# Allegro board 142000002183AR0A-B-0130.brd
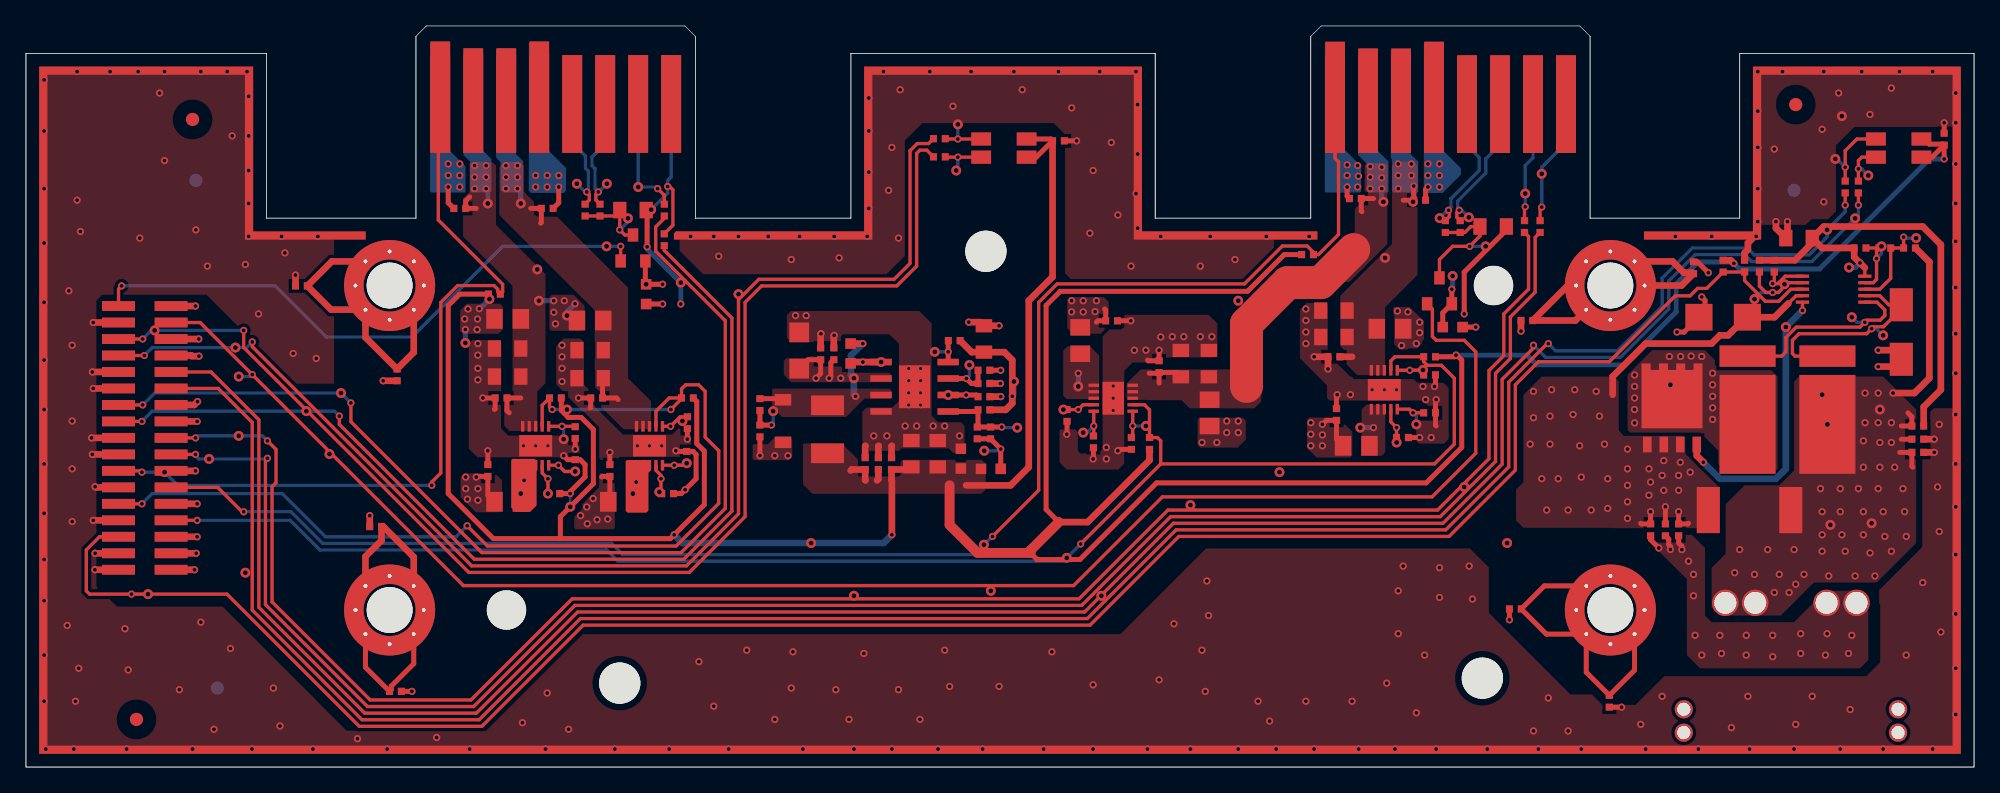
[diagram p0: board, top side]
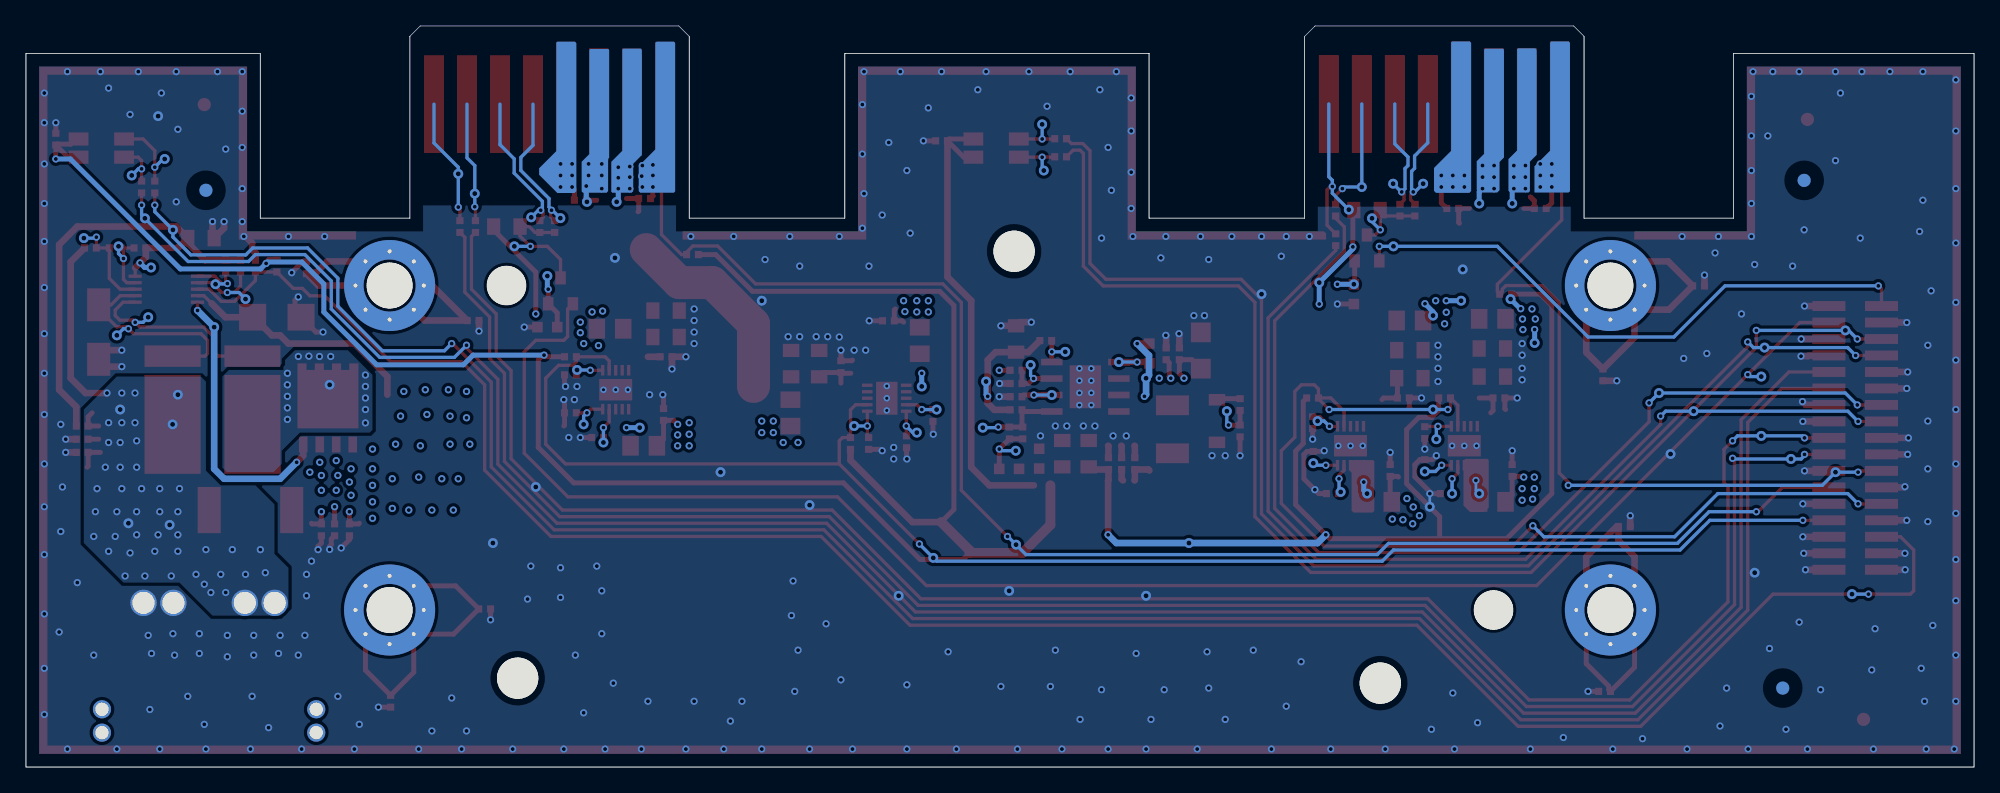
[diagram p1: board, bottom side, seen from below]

Outline 150 x 57.1 mm; copper layers: TOP, G2, V3, BOTTOM. Coordinates in mm from the lower left corner of the outline.
Outline path: 30.03,56.3 30.03,42.29 18.51,42.29 18.51,54.99 0,54.99 0,0 150,0 150,54.99 131.96,54.99 131.96,42.29 120.44,42.29 120.44,56.3 ; 51.54,56.3 51.54,42.29 63.52,42.29 63.52,54.99 86.95,54.99 86.95,42.29 98.93,42.29 98.93,56.3

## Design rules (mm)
constraint set DEFAULT: min track width 0.254
net group CLS_POWER: nets VCC_CL_FAN7F VCC_CL_FAN7R
net group DIFF_FAN7: nets FAN7_IN_PWM FAN7_OUT_PWM
net group DIFF_FAN8: nets FAN8_IN_PWM FAN8_OUT_PWM
net group CLS_GND: nets FAN7_S_GND FAN8_S_GND LGND_FAN12V LGND_VDD3P3
net group CLS_PWM: nets FAN7_PWM_P FAN8_PWM_P PWM_OUT7 PWM_OUT8

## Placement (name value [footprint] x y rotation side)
C1  1000pF/50V  [CC0402]  21.21 37.07 270 top
C2  1000pF/50V  [CC0402]  26.92 18.53 270 top
C3  1000pF/50V  [CC0402]  28.45 5.83 90 top
C4  1000pF/50V  [CC0402]  28.57 30.21 0 top
C5  1000pF  [CC0402]  33.4 43.04 90 top
C6  0.1uF  [CC0402]  35.57 22.85 0 top
C7  0.1uF/16V  [CC0402]  36.58 28.44 270 top
C8  22uF/16V  [CC0805]  37.09 32.25 270 top
C9  10uF/16V  [CC0805]  37.09 30.09 270 top
C10  1000pF  [CC0402]  40.14 43.04 90 top
C11  0.1uF/16V  [CC0402]  40.65 21.07 270 top
C12  0.1uF/16V  [CC0402]  42.29 25.77 180 top
C13  22uF/16V  [CC0805]  43.44 32.12 270 top
C14  10uF/16V  [CC0805]  43.44 29.96 270 top
C15  0.1uF  [CC0402]  43.94 28.44 270 top
C16  0.1uF/16V  [CC0402]  44.96 22.85 0 top
C17  0.1uF/16V  [CC0402]  49.41 21.07 270 top
C18  0.1uF/16V  [CC0402]  50.93 26.53 180 top
C19  2200pF/50V  [CC0402]  56.52 25.9 0 top
C20  22uF/16V  [CC1206]  59.54 32.09 180 top
C21  1nF/50V  [CC0402]  61.19 31.84 180 top
C22  0.1uF/16V  [CC0402]  62.2 31.84 180 top
C23  0.1uF/50V  [CC0603]  63.5 31.87 180 top
C24  1uF/6.3V  [CC0402]  64.62 23.38 180 top
C25  0.1uF/16V  [CC0402]  65.63 23.38 180 top
C26  1uF/6.3V  [CC0402]  66.65 23.38 180 top
C27  22uF/6.3V  [CC0805]  68.17 24.14 180 top
C28  22uF/6.3V  [CC0805]  70.21 24.14 180 top
C29  8200pF/16V  [CC0402]  71.48 32.86 90 top
C30  10uF/6.3V  [CC0603]  71.98 23.76 180 top
C31  22pF/50V  [CC0402]  73.25 25.74 180 top
C32  10pF  [CC0402]  73.76 29.55 90 top
C33  0.47uF/6.3V  [CC0402]  73.76 28.54 90 top
C34  0.1uF/16V  [CC0402]  79.5 48.25 90 top
C35  0.1uF/16V  [CC0402]  80.16 27.09 180 top
C36  0.1uF/16V  [CC0402]  83.59 34.38 270 top
C37  0.1uF/16V  [CC0402]  85.12 24.93 180 top
C38  0.1uF/16V  [CC0402]  87.25 30.85 180 top
C39  10uF/16V  [CC0805]  88.93 31.08 180 top
C40  22uF/16V  [CC0805]  91.08 31.08 180 top
C41  22uF/16V  [CC0805]  100.71 35.17 270 top
C42  10uF/16V  [CC0805]  100.71 33.14 270 top
C43  0.1uF/16V  [CC0402]  100.71 31.61 270 top
C44  0.1uF/16V  [CC0402]  100.91 27.17 0 top
C45  1000pF  [CC0402]  102.36 43.8 90 top
C46  0.1uF/16V  [CC0402]  105.99 25.39 270 top
C47  1000pF  [CC0402]  107.31 43.68 90 top
C48  0.1uF/16V  [CC0402]  108.08 30.21 270 top
C49  1000pF/50V  [CC0402]  114.68 12.18 270 top
C50  1000pF/50V  [CC0402]  115.57 34.41 270 top
C51  1000pF/50V  [CC0402]  121.92 5.07 0 top
C52  1000pF/50V  [CC0402]  125.09 18.28 0 top
C53  1000pF/50V  [CC0402]  126.24 18.28 0 top
C54  0.1uF/16V  [CC0402]  127.25 18.28 0 top
C55  1000pF/50V  [CC0402]  128.4 38.47 180 top
C56  0.1uF/16V  [CC0402]  132.33 38.6 180 top
C57  6800pF  [CC0402]  134.62 38.6 180 top
C58  1nF/50V  [CC0402]  145.67 26.28 90 top
C59  0.1uF/16V  [CC0402]  145.67 25.26 90 top
C60  1nF/50V  [CC0402]  145.67 24.25 90 top
C61  0.1uF/16V  [CC0402]  147.7 48.38 180 top
CONN1  LCB25-G3424S01C-04  [CONNM_1D27X4D05_2X17SP_36D09W]  9.15 25.36 270 top
CONN2  CONN_POWER_4P_G4  [CONN_2D3_4DP_18D2W12D3L_PIP]  135.9 12.65 180 top
D1  SS1040  [SOD123_3D28_2SP_AC]  58.29 26.66 0 top
D2  1SMA4744  [DO214AC_3D73_2SP_2D7W4D3L2D44H]  130.68 34.66 0 top
D3  P4SMAJ58A  [DIOZENER_2SP_2D6WX4D5L_AC]  144.4 33.52 0 top
H1  *SCREW_8_1  [MTH_276C138D_8DP_OSP]  28 37.1 0 top
H2  *SCREW_8_1  [MTH_276C138D_8DP_OSP]  28 12.1 0 top
H3  *SCREW_8_1  [MTH_276C138D_8DP_OSP]  122 37.1 0 top
H4  *SCREW_8_1  [MTH_276C138D_8DP_OSP]  122 12.1 0 top
L1  100MHz/5A  [LC0805]  37.09 34.53 90 top
L2  100MHz/5A  [LC0805]  37.09 20.44 90 top
L3  100MHz/5A  [LC0805]  43.44 34.41 90 top
L4  100MHz/5A  [LC0805]  45.85 20.44 90 top
L5  1.5uH/4.5A  [CHOKE_3D7_2SP_4W4D5L2H]  61.72 26.02 270 top
L6  100MHz/5A  [LC0805]  81.18 32.86 0 top
L7  100MHz/5A  [LC0805]  91.14 27.29 180 top
L8  100MHz/5A  [LC0805]  102.43 24.75 90 top
L9  100MHz/5A  [LC0805]  105.03 33.77 270 top
LED1  LED2_1  [LED_1D4X3D5_4SP_2D7W3D2L1D1H_AC]  75.3 47.69 0 top
LED2  LED2_1  [LED_1D4X3D5_4SP_2D7W3D2L1D1H_AC]  144.2 47.69 0 top
NOREF  -  []  75.3 47.69 0 top
NOREF#2  -  []  18.51 54.99 0 top
NOREF#3  -  [unnamed#2]  112.14 6.85 0 top
NOREF#4  -  []  119.64 57.1 0 top
NOREF#5  -  []  122 37.1 0 top
NOREF#6  -  []  -35.56 -22.11 0 top
NOREF#7  -  []  37 12.1 0 top
NOREF#8  -  [unnamed#2]  136.27 51.04 0 top
NOREF#9  -  []  28 37.1 0 top
NOREF#10  -  []  51.54 56.3 0 top
NOREF#11  -  [unnamed#2]  113 37.1 0 top
NOREF#12  -  []  75.3 47.69 0 top
NOREF#13  -  [unnamed#2]  12.83 49.9 0 top
NOREF#14  -  []  28 37.1 0 top
NOREF#15  -  []  113 37.1 0 top
NOREF#16  -  []  0 0 0 top
NOREF#17  -  []  120.44 56.3 0 top
NOREF#18  -  []  92.84 5.96 0 top
NOREF#19  -  []  130.85 12.65 0 top
NOREF#20  -  []  150 0 0 top
NOREF#21  -  []  0 0 0 top
NOREF#22  -  [unnamed#2]  45.72 6.47 0 top
NOREF#23  -  []  0 54.99 0 top
NOREF#24  -  []  131.96 54.99 0 top
NOREF#25  -  []  144.2 47.69 0 top
NOREF#26  -  []  18.51 42.29 0 top
NOREF#27  -  [unnamed#2]  73.91 39.74 0 top
NOREF#28  -  []  86.95 54.99 0 top
NOREF#29  -  [unnamed#2]  37 12.1 0 top
NOREF#30  -  []  98.93 56.3 0 top
NOREF#31  -  []  9.15 25.36 0 top
NOREF#32  -  [unnamed#2]  8.51 3.67 0 top
NOREF#33  -  []  37 12.1 0 top
NOREF#34  -  []  130.85 12.65 0 top
NOREF#35  -  []  28 12.1 0 top
NOREF#36  -  []  113 37.1 0 top
NOREF#37  -  []  63.52 54.99 0 top
NOREF#38  -  []  30.03 56.3 0 top
NOREF#39  -  []  325.75 -30.7 0 top
NOREF#40  -  []  511.81 -36.71 0 top
NOREF#41  -  []  0 0 0 top
NOREF#42  -  [unnamed#2]  13.08 45.2 180 bottom
NOREF#43  -  [unnamed#2]  136.14 44.44 180 bottom
NOREF#44  -  [unnamed#2]  14.73 6.08 180 bottom
Q1  N-CH  [SOT23_1D9X2D_3SP_1D3W3L_GSD]  46.74 39.99 0 top
Q2  N-CH  [SOT23_1D9X2D_3SP_1D3W3L_GSD]  108.84 36.69 0 top
Q3  N-CH/30V/200A  [SO8_3D75X1D27_5SP]  126.75 27.67 270 top
R1  10Kohm  [RC0402]  36.07 36.44 90 top
R2  4.7Kohm  [RC0402]  40.77 28.44 270 top
R3  2.8Kohm  [RC0402]  42.29 23.23 0 top
R4  0ohm  [RC0402]  43.06 42.91 0 top
R5  0ohm  [RC0402]  44.2 42.91 0 top
R6  7.5Kohm  [RC0805]  46.74 42.91 90 top
R7  0ohm  [RC0603]  47.75 36.44 180 top
R8  0ohm  [RC0402]  49.15 40.63 0 top
R9  0ohm  [RC0402]  49.15 42.91 180 top
R10  2.8Kohm  [RC0402]  50.88 23.86 0 top
R11  4.7Kohm  [RC0402]  50.93 28.44 270 top
R12  2.2ohm  [RC0402]  56.52 27.93 180 top
R13  110ohm  [RC0402]  70.33 48.41 90 top
R14  110ohm  [RC0402]  70.33 47.02 90 top
R15  0ohm  [RC0805]  73.76 32.98 0 top
R16  10Kohm  [RC0402]  73.76 30.57 90 top
R17  10Kohm  [RC0402]  73.76 27.52 90 top
R18  33.2Kohm  [RC0402]  74.27 25.74 0 top
R19  49.9ohm  [RC0603]  74.3 22.98 270 top
R20  2.8Kohm  [RC0402]  82.19 25.06 180 top
R21  4.7Kohm  [RC0402]  86.51 24.93 180 top
R22  10Kohm  [RC0402]  98.68 39.49 90 top
R23  4.7Kohm  [RC0402]  108.08 31.61 270 top
R24  2.8Kohm  [RC0402]  108.08 27.29 270 top
R25  0ohm  [RC0402]  109.29 41.64 0 top
R26  0ohm  [RC0603]  109.86 33.9 270 top
R27  0ohm  [RC0402]  110.43 41.64 0 top
R28  7.5Kohm  [RC0805]  112.97 41.64 90 top
R29  0ohm  [RC0402]  115.39 41.64 180 top
R30  0ohm  [RC0402]  116.59 41.64 0 top
R31  4.7Kohm  [RC0402]  130.68 38.6 180 top
R32  0.001ohm  [RC2512]  132.72 19.8 90 top
R33  8.87Kohm  [RC0402]  133.48 38.6 0 top
R34  0.001ohm  [RC_6D15_2SP_9D14W9D4L]  135.64 27.55 0 top
R35  0ohm  [RC0805]  136.53 40.76 270 top
R36  110ohm  [RC0402]  140.08 44.69 180 top
R37  110ohm  [RC0402]  141.1 44.69 180 top
R38  4.64Kohm  [RC0402]  141.22 39.99 90 top
R39  3.24Kohm  [RC0402]  143.13 39.99 90 top
R40  23.7Kohm  [RC0402]  145.03 39.99 90 top
U1  SY6875ADBC  [DFN_D5X3D_10SP_3WL1H_G1]  39.25 24.75 0 top
U2  Golden Finger  [GOLD_FINGER_2D54_8X2SP]  49.68 51.09 0 top
U3  SY6875ADBC  [DFN_D5X3D_10SP_3WL1H_G1]  48.01 24.75 0 top
U4  TPS54329DDAR  [SOP_1D27X5D165_8SP_3D9W_G95X130]  68.43 29.3 0 top
U5  SY6875ADBC  [DFN_D5X3D_10SP_3WL1H_G1]  83.72 28.42 270 top
U6  SY6875ADBC  [DFN_D5X3D_10SP_3WL1H_G1]  104.59 29.07 0 top
U7  Golden Finger  [GOLD_FINGER_2D54_8X2SP]  118.58 51.07 0 top
U8  LM5069MM-2/NOPB  [MSOP_D5X4D8_10SP_3WL1D09H]  139.19 36.82 90 top

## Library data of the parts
C1-C61 = C_NP
CONN1 = PIN HEADER_MALE_17PX2R
CONN2 = CONN_POWER_4P_G4
D1 = DIODE1_1
D2 = ZENER1_1
D3 = TVS1_1
H1-H4 = SCREW_8_1
L1-L4 L6-L9 = BEAD
L5 = POWER CHOKE
LED1 LED2 = LED2_1
Q1 Q2 = NMOS1_1
Q3 = NMOS1_6
R1-R15 R17-R33 R35-R40 = R: tolerance: 1%
R16 = R: room: 71
R34 = R_4P: tolerance: 1%
U1 U3 U5 U6 = MONITOR_CUR_SILERGY_SY6875
U2 U7 = Golden Finger
U4 = DC_DC_TI_TPS54329
U8 = HOT SWAP_NS_LM5069

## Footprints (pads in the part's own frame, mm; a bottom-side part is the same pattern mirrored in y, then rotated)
CC0402
  rect 0.559x0.539 smd: 1(0,0.454) 2(0,-0.454)
CC0603
  rect 0.813x0.813 smd: 1(0,0.762) 2(0,-0.762)
CC0805
  rect 1.27x1.016 smd: 1(0,1.016) 2(0,-1.016)
CC1206
  rect 1.524x1.524 smd: 1(0,1.397) 2(0,-1.397)
CHOKE_3D7_2SP_4W4D5L2H
  rect 1.524x2.54 smd: 1(-1.85,0) 2(1.85,0)
CONN_2D3_4DP_18D2W12D3L_PIP
  round 1.397 hole 1.016: G1(-8.25,10) G2(-8.25,8.2) G3(8.25,10) G4(8.25,8.2)
  round 2.032 hole 1.702: P1(5.05,0) P2(2.75,0) P3(-2.75,0) P4(-5.05,0)
CONNM_1D27X4D05_2X17SP_36D09W
  rect 0.762x2.54 smd: 1(-10.16,-2.025) 2(-10.16,2.025) 3(-8.89,-2.025) 4(-8.89,2.025) 5(-7.62,-2.025) 6(-7.62,2.025) 7(-6.35,-2.025) 8(-6.35,2.025) 9(-5.08,-2.025) 10(-5.08,2.025) 11(-3.81,-2.025) 12(-3.81,2.025) 13(-2.54,-2.025) 14(-2.54,2.025) 15(-1.27,-2.025) 16(-1.27,2.025) 17(0,-2.025) 18(0,2.025) 19(1.27,-2.025) 20(1.27,2.025) 21(2.54,-2.025) 22(2.54,2.025) 23(3.81,-2.025) 24(3.81,2.025) 25(5.08,-2.025) 26(5.08,2.025) 27(6.35,-2.025) 28(6.35,2.025) 29(7.62,-2.025) 30(7.62,2.025) 31(8.89,-2.025) 32(8.89,2.025) 33(10.16,-2.025) 34(10.16,2.025)
DFN_D5X3D_10SP_3WL1H_G1
  rect 0.254x0.813 smd: 1(-1,-1.5) 2(-0.5,-1.5) 3(0,-1.5) 4(0.5,-1.5) 5(1,-1.5) 6(1,1.5) 7(0.5,1.5) 8(0,1.5) 9(-0.5,1.5) 10(-1,1.5)
  rect 2.54x1.651 smd: G1(0,0)
DIOZENER_2SP_2D6WX4D5L_AC
  rect 1.778x2.54 smd: A(0,-2.1) C(0,2.1)
DO214AC_3D73_2SP_2D7W4D3L2D44H
  rect 2.083x2.057 smd: A(-1.865,0) C(1.865,0)
GOLD_FINGER_2D54_8X2SP
  rect 1.524x7.518 smd: 1(0,0) 2(-2.54,0) 3(-5.08,0) 4(-7.62,0) 9(0,0) 10(-2.54,0) 11(-5.08,0) 12(-7.62,0) 13(-10.16,0) 14(-12.7,0) 15(-15.24,0) 16(-17.78,0)
  rect 1.524x8.56 smd: 5(-10.16,0.533) 8(-17.78,0.533)
  rect 1.524x8.052 smd: 6(-12.7,0.267) 7(-15.24,0.267)
LC0805
  rect 1.524x1.27 smd: 1(0,1.016) 2(0,-1.016)
LED_1D4X3D5_4SP_2D7W3D2L1D1H_AC
  rect 1.524x1.016 smd: A1(1.75,-0.7) A2(1.75,0.7) C1(-1.75,-0.7) C2(-1.75,0.7)
MSOP_D5X4D8_10SP_3WL1D09H
  rect 0.254x1.016 smd: 1(-1,-2.4) 2(-0.5,-2.4) 3(0,-2.4) 4(0.5,-2.4) 5(1,-2.4) 6(1,2.4) 7(0.5,2.4) 8(0,2.4) 9(-0.5,2.4) 10(-1,2.4)
MTH_276C138D_8DP_OSP
  round 3.505 hole 3.505 unplated: (0,0)
  round 0.889 hole 0.305: 1(0,2.629) 2(1.859,1.859) 3(2.629,0) 4(1.859,-1.859) 5(0,-2.629) 6(-1.859,-1.859) 7(-2.629,0) 8(-1.859,1.859)
RC0402
  rect 0.559x0.539 smd: 1(0,0.454) 2(0,-0.454)
RC0603
  rect 0.813x0.813 smd: 1(0,0.762) 2(0,-0.762)
RC0805
  rect 1.27x1.016 smd: 1(0,1.016) 2(0,-1.016)
RC2512
  rect 3.556x1.778 smd: 1(0,3.175) 2(0,-3.175)
RC_6D15_2SP_9D14W9D4L
  rect 4.318x1.651 smd: 1(-3.075,4.115) 2(3.075,4.115)
  rect 4.318x7.62 smd: 3(-3.075,-1.145) 4(3.075,-1.145)
SO8_3D75X1D27_5SP
  rect 1.219x0.66 smd: 1(2.825,-1.905) 2(2.825,-0.635) 3(2.825,0.635) 4(2.825,1.905)
  custom 1.175x1.175 smd: 5(-0.925,0)
SOD123_3D28_2SP_AC
  rect 1.27x0.889 smd: A(0,-1.64) C(0,1.64)
SOP_1D27X5D165_8SP_3D9W_G95X130
  rect 1.651x0.508 smd: 1(-2.582,1.905) 2(-2.582,0.635) 3(-2.582,-0.635) 4(-2.582,-1.905) 5(2.582,-1.905) 6(2.582,-0.635) 7(2.582,0.635) 8(2.582,1.905)
  rect 2.413x3.302 smd: G1(0,0)
SOT23_1D9X2D_3SP_1D3W3L_GSD
  rect 0.813x1.016 smd: D(0,1) G(-0.95,-1) S(0.95,-1)
unnamed#2
  round 3.175 hole 3.175 unplated: (0,0)

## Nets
GND: C1.2 C2.2 C3.2 C4.2 C5.1 C6.1 C7.2 C8.2 C9.2 C10.2 C11.1 C12.1 C13.2 C14.2 C15.2 C16.1 C17.1 C18.1 C19.2 C20.2 C21.2 C22.2 C24.2 C25.2 C26.2 C27.2 C28.2 C30.2 C32.2 C33.2 C34.2 C35.1 C36.1 C37.1 C38.2 C39.2 C40.2 C41.2 C42.2 C43.2 C44.1 C45.1 C46.1 C47.2 C48.1 C49.2 C50.2 C51.2 C52.2 C53.2 C54.2 C55.2 C56.2 C59.2 C60.2 C61.2 CONN1.2 CONN1.3 CONN1.6 CONN1.8 CONN1.9 CONN1.11 CONN1.14 CONN1.16 CONN1.17 CONN1.19 CONN1.22 CONN1.23 CONN1.26 CONN1.27 CONN1.30 CONN1.31 CONN1.32 CONN1.33 CONN1.34 CONN2.P3(POWER_1N) CONN2.P4(POWER_2N) D1.A D2.A D3.A R3.1 R7.1 R10.1 R15.1 R20.1 R24.1 R26.1 R35.2 U1.G1 U2.5 U2.8 U3.G1 U4.4(GND) U4.G1 U5.G1 U6.G1 U7.5 U7.8
GND_1: C1.1 C4.1 H1.1 H1.2 H1.3 H1.4 H1.5 H1.6 H1.7 H1.8
GND_2: C50.1 C55.1 H3.1 H3.2 H3.3 H3.4 H3.5 H3.6 H3.7 H3.8
GND_3: C49.1 C51.1 H4.1 H4.2 H4.3 H4.4 H4.5 H4.6 H4.7 H4.8
GND_4: C2.1 C3.1 H2.1 H2.2 H2.3 H2.4 H2.5 H2.6 H2.7 H2.8
VCC_12P_FAN7_IN: C5.2 C7.1 C8.1 C9.1 L1.2 U1.8(OUT8) U1.9(OUT9) U1.10(OUT0) U2.7
VCC_12P_FAN7_OUT: C10.1 C13.1 C14.1 C15.1 L3.2 U2.6 U3.8(OUT8) U3.9(OUT9) U3.10(OUT0)
VCC_12P_FAN8_IN: C38.1 C39.1 C40.1 C45.2 L7.2 U5.8(OUT8) U5.9(OUT9) U5.10(OUT0) U7.7
VCC_12P_FAN8_OUT: C41.1 C42.1 C43.1 C47.1 L9.2 U6.8(OUT8) U6.9(OUT9) U6.10(OUT0) U7.6
VCC_CL_FAN7F: L4.2 U3.1(IN1) U3.2(IN2) U3.3(IN3)
VCC_CL_FAN7R: L2.2 U1.1(IN1) U1.2(IN2) U1.3(IN3)
VCC_CL_FAN8F: L8.2 U6.1(IN1) U6.2(IN2) U6.3(IN3)
VCC_CL_FAN8R: L6.2 U5.1(IN1) U5.2(IN2) U5.3(IN3)
VDD3P3: C24.1 C25.1 C26.1 C27.1 C28.1 C30.1 C34.1 C61.1 L5.2 LED1.A1 LED1.A2 LED2.A1 LED2.A2 R1.1 R2.1 R11.1 R19.2 R21.1 R22.1 R23.1 R31.2
VDD3P3_BODE: C31.1 R18.2 R19.1
VDD3P3_EN: C32.1 R16.1 U4.7(EN)
BS_VDD3P3: C23.1 U4.1(BS)
EN_FAN7: CONN1.25 R2.2 R11.2 U1.7(EN) U3.7(EN)
EN_FAN8: CONN1.28 R21.2 R23.2 U5.7(EN) U6.7(EN)
FAN7_IN_PWM: R4.1 U2.4
FAN7_LED_G: CONN1.5 R14.1
FAN7_LED_G1: LED1.C1 R14.2
FAN7_LED_R: CONN1.7 R13.1
FAN7_LED_R1: LED1.C2 R13.2
FAN7_OUT_PWM: R5.1 U2.3
FAN7_PRESENT: CONN1.21 R1.2 U2.16
FAN7_PWM_P: Q1.D R4.2 R5.2 R6.1
FAN7_S_GND: Q1.S R7.2
FAN7_SENSOR_IN: CONN1.13 R9.1
FAN7_SENSOR_IN_R: R9.2 U2.2
FAN7_SENSOR_OUT: CONN1.15 R8.2
FAN7_SENSOR_OUT_R: R8.1 U2.1
FAN7F_VCP: C17.2 U3.4(VCP)
FAN7R_VCP: C11.2 U1.4(VCP)
FAN8_IN_PWM: R25.1 U7.4
FAN8_LED_G: CONN1.10 R37.1
FAN8_LED_G1: LED2.C1 R37.2
FAN8_LED_R: CONN1.12 R36.1
FAN8_LED_R1: LED2.C2 R36.2
FAN8_OUT_PWM: R27.1 U7.3
FAN8_PRESENT: CONN1.24 R22.2 U7.16
FAN8_PWM_P: Q2.D R25.2 R27.2 R28.1
FAN8_S_GND: Q2.S R26.2
FAN8_SENSOR_IN: CONN1.18 R29.1
FAN8_SENSOR_IN_R: R29.2 U7.2
FAN8_SENSOR_OUT: CONN1.20 R30.2
FAN8_SENSOR_OUT_R: R30.1 U7.1
FAN8F_VCP: C46.2 U6.4(VCP)
FAN8R_VCP: C35.2 U5.4(VCP)
FAN_12V: C6.2 C16.2 C20.1 C21.1 C22.1 C36.2 C44.2 C52.1 C53.1 C54.1 D2.C L1.1 L2.1 L3.1 L4.1 L6.1 L7.1 L8.1 L9.1 Q3.1(S1) Q3.2(S2) Q3.3(S3) R6.2 R16.2 R28.2 R32.1 U4.2(IN) U8.9(OUT)
FAN_12V_PDU: C58.1 C59.1 C60.1 CONN2.P1(POWER_1P) CONN2.P2(POWER_2P) R32.2 R34.4 R40.2
FAN_TOP_HS_PGD: C56.1 CONN1.29 R31.1 U8.8(PGD)
FB_VDD3P3: C31.2 R17.1 R18.1 U4.5(FB)
HS_GATE: Q3.4(G) U8.10(GATE)
HS_MOS_D: Q3.5(D) R34.3
HS_OV: R38.2 R39.1 U8.4(OVLO)
HS_PWR: R33.2 U8.7(PWR)
HS_SENSE: R34.1 U8.1(SENSE)
HS_TIMER: C57.1 U8.6(TIMER)
HS_UV: R39.2 R40.1 U8.3(UVLO)
HS_VIN: D3.C R34.2 U8.2(VIN)
ILIM_FAN7F: R10.2 U3.5(ILIM)
ILIM_FAN7R: R3.2 U1.5(ILIM)
ILIM_FAN8F: R24.2 U6.5(ILIM)
ILIM_FAN8R: R20.2 U5.5(ILIM)
LGND_FAN12V: C57.2 C58.2 R33.1 R35.1 R38.1 U8.5(GND)
LGND_VDD3P3: C29.2 R15.2 R17.2
PWM_OUT7: CONN1.1 Q1.G
PWM_OUT8: CONN1.4 Q2.G
SS_VDD3P3: C29.1 U4.8(SS)
SST_FAN7F: C18.2 U3.6(SST)
SST_FAN7R: C12.2 U1.6(SST)
SST_FAN8F: C48.2 U6.6(SST)
SST_FAN8R: C37.2 U5.6(SST)
SW_VDD3P3: C23.2 D1.C L5.1 R12.2 U4.3(SW)
SW_VDD3P3_PLL_C: C19.1 R12.1
VREG5_VDD3P3: C33.1 U4.6(VREG5)

Pads without a net: CONN2 G1 G2 G3 G4; U2 9 10 11 12 13 14 15; U7 9 10 11 12 13 14 15

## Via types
v1: diameter 0.762, hole 0.381, TOP to BOTTOM, 95 vias
v2: diameter 0.559, hole 0.305, TOP to BOTTOM, 634 vias
v3: diameter 0.508, hole 0.254, TOP to BOTTOM, 20 vias

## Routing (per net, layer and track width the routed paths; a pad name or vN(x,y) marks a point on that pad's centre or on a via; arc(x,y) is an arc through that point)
GND: length 115.9
  TOP w0.381: 108.58,26.28 108.53,26.33 R24.1 108.53,28.26 v2(108.58,28.31) ; v2(127.13,33.52) 127.67,33.52 D2.A 129.29,35.13 129.29,35.97 v2(129.03,36.22) ; v2(32.51,44.69) 32.51,43.48 C5.1 ; C17.1 50.46,21.07 v2(50.76,21.37) 51.6,22.21 51.6,24.08 51.36,24.32 R10.1 50.09,24.32 v2(50.04,24.37) ; C47.2 107.77,44.51 v2(107.95,44.69) ; v2(82.17,23.74) 82.19,23.76 R20.1 ; C46.1 v2(107.31,25.39) ; v2(129.54,38.09) 128.7,38.92 C55.2 ; C3.2 v2(29.72,5.83) ; 86.36,31.36 86.41,31.3 C38.2 v2(87.25,32.12) ; C51.2 v2(122.86,4.61) ; C54.2 127.25,17.26 127.51,17.01 v2(127.51,16.75) ; v2(41.4,23.99) 41.71,23.68 R3.1 42.67,23.68 43.05,23.3 43.05,22.36 41.9,21.21 v2(41.9,21.07) C11.1 ; C37.1 84.18,24.48 v2(84.07,24.37) ; C19.2 v2(56.52,23.99) ; v2(101.73,44.69) 101.73,43.98 C45.1 ; 43.43,27.67 43.49,27.73 C15.2 v2(42.55,28.44) ; C34.2 v2(80.9,48.25) ; R7.1 v2(49.02,35.68) ; C12.1 v2(42.29,24.5) ; 85.09,34.41 v2(85.07,34.38) C36.1 ; v2(126.62,16.76) 126.62,17.01 126.49,17.13 126.49,17.57 C53.2 ; v2(108.46,29.33) 108.53,29.4 C48.1 ; v2(35.18,28.44) C7.2 36.13,27.61 36.07,27.55 ; v2(35.56,24.37) 35.57,24.37 C6.1 ; v2(125.73,16.88) 125.09,17.51 C52.2 ; C10.2 41.02,43.47 v2(41.02,44.69) ; C18.1 v2(50.93,25.26) ; C44.1 100.91,28.63 v2(100.97,28.69) ; R26.1 v2(111.63,33.9) ; C61.2 v2(147.7,49.65) ; C49.2 v2(114.23,11.34) ; C35.1 80.16,25.67 v2(80.14,25.64) ; C16.1 v2(44.96,24.25)
  TOP w0.508: v2(100.26,30.67) C43.2 v2(99.19,31.61) ; CONN1.19 v2(5.11,24.09) ; CONN1.27 v2(5.18,19.01) ; v2(133.22,40.88) 133.1,40.88 132.59,40.37 132.59,39.87 132.33,39.61 C56.2 ; CONN1.2 v2(13.05,35.52) ; CONN1.33 v2(5.31,15.2) ; v2(13.32,31.66) 12.78,31.66 12.73,31.71 CONN1.8 ; C50.2 v2(115.12,33.59) ; C2.2 v2(26.47,19.37) ; 64.64,24.75 64.62,24.73 C24.2 ; v2(62.23,33.26) 62.2,33.24 C22.2 ; CONN1.17 v2(5.05,25.36) ; CONN1.16 v2(13.18,26.63) ; CONN1.31 v2(5.32,16.47) ; C33.2 v2(75.06,28.54) ; C25.2 65.63,24.73 65.66,24.75 ; CONN1.14 12.95,27.9 v2(13.21,28.16) ; CONN1.3 v2(5.18,34.25) ; CONN1.26 v2(13.18,20.28) ; CONN1.9 v2(5.11,30.44) ; CONN1.11 v2(5.18,29.17) ; v2(61.21,33.39) 61.19,33.36 C21.2 ; v2(74.93,34) R15.1 73.48,34.28 v2(72.59,34.28) ; CONN1.6 v2(13.31,32.98) ; 66.67,24.75 66.65,24.73 C26.2 ; v2(135.64,42.03) 135.64,40.88 R35.2 134.75,41.52 v2(134.75,42.03) ; C60.2 v2(146.94,24.25) ; CONN1.32 v2(13.11,16.47) ; C32.2 v2(75.03,29.55) ; CONN1.22 v2(13.05,22.82) ; C1.2 v2(20.75,37.91) ; CONN1.23 5.37,21.55 v2(5.32,21.6) ; CONN1.30 v2(13.18,17.74) ; v2(142.62,30.85) 143.83,30.85 D3.A 143.7,32.12 v2(142.62,32.12) ; CONN1.34 v2(12.98,15.2) ; C59.2 v2(146.94,25.26) ; C4.2 v2(27.51,29.76)
  BOTTOM w0.203: v1(41.91,20.05) 41.91,21.06
  BOTTOM w0.381: 41.91,21.06 v2(41.9,21.07)
  vias: v1(16.89,14.97) v1(23.37,24.12) v1(39.37,38.34) v1(54.86,36.44) v1(63.75,13.2) v1(74.3,13.58) v1(82.8,13.2) v1(89.66,20.18) v1(93.34,35.93) v1(96.52,22.72) v1(104.65,39.23) v1(110.74,21.58) v1(114.05,17.26) v1(139.83,50.15) v2(1.4,52.95) v2(1.4,49.01) v2(1.4,44.57) v2(1.4,40.37) v2(1.4,35.8) v2(1.4,31.36) v2(1.4,27.55) v2(1.4,23.36) v2(1.4,19.55) v2(1.4,15.99) v2(1.4,12.82) v2(1.4,8.62) v2(1.4,5.07) v2(1.52,1.39) v2(3.17,10.91) v2(3.3,36.69) v2(3.56,32.5) v2(3.56,26.66) v2(3.56,22.98) v2(3.56,18.91) v2(3.68,1.39) v2(3.81,5.07) v2(3.94,53.58) v2(3.94,43.68) v2(4.06,7.61) v2(4.19,41.26) v2(6.48,53.58) v2(7.62,10.66) v2(7.75,1.39) v2(7.87,7.48) v2(8.64,53.58) v2(8.76,40.76) v2(10.29,51.93) v2(10.67,53.58) v2(10.67,46.72) v2(11.81,5.96) v2(12.83,1.39) v2(13.08,41.39) v2(13.46,53.58) v2(13.46,11.16) v2(13.97,38.6) v2(14.48,2.91) v2(15.49,53.58) v2(15.75,9.13) v2(15.88,48.63) v2(16.89,38.72) v2(17.02,53.58) v2(17.14,51.68) v2(17.14,48.63) v2(17.14,45.96) v2(17.14,43.42) v2(17.14,40.88) v2(17.4,1.39) v2(17.91,34.91) v2(19.05,6.08) v2(19.56,3.16) v2(19.68,40.88) v2(19.94,39.61) v2(20.57,31.87) v2(22.1,1.39) v2(22.35,31.48) v2(22.48,40.88) v2(25.53,2.18) v2(27.81,1.39) v2(31.62,2.27) v2(32.51,46.47) v2(32.51,45.58) v2(33.4,46.47) v2(33.4,45.58) v2(33.4,44.69) v2(34.16,1.39) v2(34.8,32.63) v2(34.8,31.74) v2(34.8,30.72) v2(34.8,29.83) v2(38.23,3.42) v2(39.24,45.58) v2(39.24,44.69) v2(40.01,1.39) v2(40.13,45.58) v2(40.13,44.69) v2(40.13,5.7) v2(41.02,45.58) v2(41.27,32.5) v2(41.27,31.61) v2(41.27,30.72) v2(41.27,29.71) v2(41.78,2.91) v2(45.34,1.39) v2(49.53,1.39) v2(51.18,40.88) v2(51.82,8.12) v2(52.96,40.88) v2(52.96,4.69) v2(53.34,39.36) v2(54.1,1.39) v2(54.86,40.88) v2(55.5,9.01) v2(57.15,40.88) v2(57.66,23.99) v2(57.66,3.67) v2(58.67,23.99) v2(58.93,39.1) v2(58.93,6.08) v2(59.05,8.88) v2(59.26,34.79) v2(59.56,40.88) v2(59.82,1.39) v2(60.07,34.79) v2(62.23,40.88) v2(62.36,5.96) v2(62.61,39.23) v2(63.37,3.67) v2(63.75,1.39) v2(64.52,8.75) v2(64.77,40.88) v2(64.9,51.55) v2(64.9,49.01) v2(64.9,45.84) v2(64.9,43.04) v2(65.28,25.52) v2(66.04,53.58) v2(66.29,25.52) v2(66.42,44.44) v2(66.67,47.74) v2(66.67,1.39) v2(67.18,40.76) v2(67.18,5.96) v2(67.31,52.19) v2(67.69,26.28) v2(68.58,26.28) v2(68.83,3.67) v2(69.6,53.58) v2(69.85,26.28) v2(70.23,1.39) v2(70.74,26.28) v2(70.74,9.01) v2(71.12,6.21) v2(71.37,50.92) v2(71.88,25.52) v2(72.77,53.58) v2(73.66,1.39) v2(74.93,6.21) v2(76.07,53.58) v2(76.71,52.19) v2(78.36,1.39) v2(78.99,8.88) v2(79.5,53.58) v2(80.52,50.79) v2(81.92,41.14) v2(82.17,45.96) v2(82.17,6.34) v2(82.17,1.39) v2(82.68,53.58) v2(83.19,24.63) v2(83.19,23.74) v2(83.57,48.12) v2(84.07,42.53) v2(85.09,38.6) v2(85.34,32.12) v2(85.47,53.58) v2(85.47,44.18) v2(85.6,51.04) v2(85.6,47.23) v2(85.6,41.52) v2(86.23,32.12) v2(86.36,1.39) v2(87.25,6.72) v2(87.38,40.88) v2(87.38,33.14) v2(88.27,33.16) v2(88.39,11.04) v2(89.15,33.16) v2(89.66,1.39) v2(90.42,38.6) v2(90.42,33.16) v2(90.55,9.01) v2(90.81,5.83) v2(90.93,14.34) v2(91.06,11.67) v2(91.19,40.88) v2(91.31,33.16) v2(93.09,39.1) v2(93.34,1.39) v2(94.87,5.07) v2(95.5,40.88) v2(95.76,3.54) v2(96.27,1.39) v2(98.55,35.29) v2(98.55,34.41) v2(98.55,33.52) v2(98.55,32.63) v2(98.55,5.07) v2(98.81,40.88) v2(99.19,1.39) v2(101.73,46.39) v2(101.73,45.58) v2(101.98,28.69) v2(102.11,5.07) v2(102.54,46.34) v2(102.54,44.69) v2(102.59,45.53) v2(102.62,1.39) v2(104.78,6.47) v2(105.41,1.39) v2(105.66,13.58) v2(105.66,10.28) v2(106.05,15.48) v2(107.06,4.18) v2(107.57,29.33) v2(107.7,8.62) v2(107.77,28.31) v2(107.95,46.47) v2(107.95,45.58) v2(108.2,25.39) v2(108.58,1.39) v2(108.84,46.47) v2(108.84,45.58) v2(108.84,44.69) v2(108.84,15.36) v2(108.84,13.07) v2(111.12,15.48) v2(111.38,12.94) v2(112.52,1.39) v2(116.08,2.78) v2(116.46,1.39) v2(117.22,5.32) v2(118.75,2.78) v2(119.76,1.39) v2(124.33,3.29) v2(124.71,1.39) v2(125.98,5.45) v2(127,40.88) v2(128.02,15.86) v2(128.4,14.85) v2(128.4,13.2) v2(128.52,10.15) v2(128.78,1.39) v2(129.03,8.62) v2(129.79,40.88) v2(130.43,10.15) v2(130.56,8.75) v2(131.32,3.04) v2(132.46,10.15) v2(132.46,8.62) v2(132.59,5.45) v2(132.72,1.39) v2(133.35,53.58) v2(133.35,50.53) v2(133.35,47.74) v2(133.35,44.57) v2(133.35,42.03) v2(134.49,10.15) v2(134.49,8.5) v2(134.62,47.61) v2(135.25,53.58) v2(136.14,1.39) v2(136.27,3.29) v2(136.65,10.28) v2(136.65,8.75) v2(137.54,5.45) v2(138.3,49.14) v2(138.43,53.58) v2(138.43,43.55) v2(138.56,8.62) v2(138.68,10.28) v2(139.57,51.93) v2(139.7,1.39) v2(140.34,8.75) v2(140.46,4.43) v2(140.59,10.15) v2(141.35,53.58) v2(141.99,50.28) v2(143,1.39) v2(143.64,52.31) v2(144.27,53.58) v2(144.78,8.62) v2(146.05,14.21) v2(146.81,53.58) v2(146.81,1.39) v2(147.19,21.58) v2(147.32,26.4) v2(147.32,18.15) v2(147.45,10.4) v2(148.59,51.93) v2(148.59,49.65) v2(148.59,46.47) v2(148.59,43.42) v2(148.59,40.5) v2(148.59,36.95) v2(148.59,33.39) v2(148.59,30.34) v2(148.59,27.17) v2(148.59,23.36) v2(148.59,20.05) v2(148.59,16.37) v2(148.59,11.8) v2(148.59,7.61) v2(148.59,4.05) v3(38.31,24.75) v3(39.25,24.75) v3(40.19,24.75) v3(47.07,24.75) v3(48.01,24.75) v3(48.95,24.75) v3(67.97,30.71) v3(67.97,29.77) v3(67.97,28.83) v3(67.97,27.89) v3(68.88,30.71) v3(68.88,29.77) v3(68.88,28.83) v3(68.88,27.89) v3(83.72,29.36) v3(83.72,28.42) v3(83.72,27.48) v3(103.65,29.07) v3(104.59,29.07) v3(105.53,29.07)
GND_1: length 21.2
  TOP w0.508: H1.8 23.55,38.96 C1.1 23.49,35.24 H1.6 26.14,33.1 C4.1 29.86,31.95 H1.4
GND_2: length 18
  TOP w0.508: H3.3 127.48,37.1 C55.1 128.32,38.09 127.66,38.09 126.78,38.96 H3.2 ; H3.6 119.31,34.41 C50.1 118.72,37.1 H3.7
GND_3: length 22.5
  TOP w0.381: H4.8 116.91,13.96 C49.1 117.07,10.24 H4.6 120.14,7.3 C51.1 123.86,7.46 H4.4
GND_4: length 21.1
  TOP w0.381: H2.6 26.14,7.68 C3.1 28.13,5.97 28.13,6.24 29.86,7.96 H2.4
  TOP w0.508: H2.2 29.86,16.18 27.51,18.53 C2.1 27.38,17.46 26.14,16.22 H2.8
VCC_12P_FAN7_IN: length 5.3
  TOP w0.381: 34.16,43.93 33.86,43.62 C5.2 34.67,43.04 ; 38.1,28.44 C7.1 37.04,27.47 37.21,27.29
  BOTTOM w0.381: v2(35.43,44.57) 35.56,44.44 v1(35.56,43.42)
  vias: v2(34.54,46.34) v2(34.54,45.45) v2(34.54,44.57) v2(35.43,46.34) v2(35.43,45.45)
VCC_12P_FAN7_OUT: length 6
  TOP w0.381: 39.62,41.9 39.68,41.96 C10.1 38.86,43.04 ; 45.59,28.31 45.47,28.44 C15.1 44.4,29.9 C14.1
  BOTTOM w0.381: v2(37.85,44.57) 38.1,44.31 v1(38.1,43.42)
  vias: v2(36.96,46.34) v2(36.96,45.45) v2(36.96,44.57) v2(37.85,46.34) v2(37.85,45.45)
VCC_12P_FAN8_IN: length 21.9
  TOP w0.381: C39.1 88.6,30.39 C38.1 ; C38.1 87.25,29.58 ; C38.1 87.2,30.34 86.49,30.34 ; 102.87,42.79 102.82,42.84 C45.2 103.76,43.8
  TOP w2.54: 102.23,39.87 99.69,37.33 97.16,37.33 93.98,34.15 93.98,29.33
  BOTTOM w0.381: v2(104.39,44.57) 104.39,43.68 v1(104.52,43.55)
  vias: v2(103.5,46.27) v2(103.5,45.45) v2(103.5,44.57) v2(104.39,46.22) v2(104.39,45.4)
VCC_12P_FAN8_OUT: length 4.1
  TOP w0.381: 106.05,43.68 C47.1 v2(106.86,44.77)
  TOP w0.508: C43.1 102.11,31.61
  BOTTOM w0.381: v1(106.81,43.55) 106.86,43.6 v2(106.86,44.77)
  vias: v2(105.66,46.47) v2(105.66,45.58) v2(105.66,44.57) v2(106.68,46.47) v2(106.68,45.58)
VCC_CL_FAN7F: length 1
  BOTTOM w0.381: v2(46.99,21.96) 46.99,21.32 v1(46.74,21.07)
VCC_CL_FAN7R: length 1.1
  BOTTOM w0.203: v2(38.35,22.09) 38.35,21.32 v1(38.1,21.07)
VCC_CL_FAN8F: length 1
  BOTTOM w0.381: v1(102.74,26.15) v2(103.76,26.15)
VCC_CL_FAN8R: length 1
  BOTTOM w0.381: v2(81.03,30.34) v1(81.03,29.33)
VDD3P3: length 284.8
  TOP w0.381: 41.15,17.6 35.98,17.6 32.51,21.07 32.51,35.56 33.39,36.44 R1.1 ; 41.15,17.6 49.62,17.6 v2(49.91,17.9) 52.24,20.22 52.24,24.34 51.65,24.93 51.65,28.17 R11.1 ; 41.15,17.6 41.15,19.29 43.69,21.83 43.69,26 42.75,26.94 41.76,26.94 41.22,27.47 R2.1 ; C61.1 147.63,47.99 146.56,47.99 146.16,48.39 LED2.A2 ; C61.1 146.77,46.99 LED2.A1 ; C61.1 v2(147.7,46.85) ; 79.53,18.87 78.55,19.85 78.55,35.57 79.64,36.65 94.06,36.65 96.89,39.49 R22.1 ; 77.34,16.5 77.85,15.99 81.15,15.99 87.06,21.9 107.82,21.9 110.55,24.63 110.55,31.36 110.17,31.74 v2(110.11,31.74) 109.98,31.61 R23.1 ; LED1.A1 77.79,46.99 C34.1 78.91,48.39 LED1.A2
  TOP w0.508: 63.5,22.85 63.58,22.93 C24.1 64.62,22.11 64.64,22.09 ; C25.1 65.63,22.19 65.53,22.09 ; C34.1 79.05,37.77 77.22,35.94 77.22,23.1 75.82,21.71 72.39,21.71 ; 79.53,18.87 81.75,18.87 86.51,23.64 R21.1 ; C27.1 67.97,22.93 C26.1 66.65,22.11 66.67,22.09 v2(66.67,17.9) ; v2(131.51,38.8) 131.26,39.05 R31.2
  TOP w0.762: 71.12,21.71 71.12,18.66 73.28,16.5 77.34,16.5 77.34,16.69 79.53,18.87
  BOTTOM w0.381: v2(147.7,46.85) 146.58,46.85 138.11,38.38 131.93,38.38 v2(131.51,38.8) 131.4,38.91 128.76,38.91 127.06,37.22 127.06,35.06 123,30.99 116.32,30.99 115.57,31.74 v2(110.11,31.74)
  BOTTOM w0.508: v2(66.67,17.9) 66.04,17.26 v1(60.45,17.26) 50.55,17.26 v2(49.91,17.9)
VDD3P3_BODE: length 5
  TOP w0.381: C31.1 R18.2 v2(75.06,24.5) R19.1
  BOTTOM w0.254: v2(75.06,24.5) 74.93,24.37 v1(73.79,24.37)
VDD3P3_EN: length 4.6
  TOP w0.381: R16.1 C32.1 72.8,29.55 v2(72.42,29.93) U4.7
  BOTTOM w0.254: v1(72.64,30.98) 72.64,30.16 v2(72.42,29.93)
BS_VDD3P3: length 3.8
  TOP w0.508: v1(65.85,31.2) v2(64.44,31.2) 63.6,31.2 C23.1
  BOTTOM w0.254: v1(65.85,31.2) v2(64.44,31.2)
EN_FAN7: length 79.5
  TOP w0.254: CONN1.25 v2(8.93,20.28) ; v2(33.97,18.59) 35.53,17.03 50.06,17.03 53.34,20.31 53.34,24.37 52.3,25.41 52.3,28.94 51.79,29.45 50.8,29.45 50.48,29.13 R11.2 ; R11.2 50.48,28.37 v2(49.66,27.55) ; R11.2 49.53,28.44 48.51,27.42 U3.7 ; U1.7 39.75,27.87 R2.2 40.31,27.75 v2(40.51,27.55)
  BOTTOM w0.254: v2(8.93,20.28) 9.72,21.07 19.73,21.07 23.05,17.74 33.12,17.74 33.57,18.19 33.57,18.19 v2(33.97,18.59) ; v2(40.51,27.55) v1(41.66,27.55) v2(49.66,27.55)
EN_FAN8: length 121.9
  TOP w0.254: v2(81.21,17.19) 87.38,23.36 ; 87.38,23.36 108.46,23.36 109.98,24.88 109.98,29.96 108.99,30.95 107.9,30.95 107.62,31.23 R23.2 105.41,31.61 105.09,31.29 U6.7 ; 87.38,23.36 87.38,25.13 87.12,25.39 R21.2 86.51,27.52 86.12,27.92 U5.7 ; CONN1.28 v2(13.18,19.01)
  BOTTOM w0.254: v2(81.21,17.19) v1(80.14,16.12) 79.88,15.86 45.57,15.86 44.7,16.73 22.63,16.73 20.35,19.01 v2(13.18,19.01)
FAN7_IN_PWM: length 9.5
  TOP w0.254: v2(43.18,44.31) 43.38,44.12 43.38,43.69 R4.1
  BOTTOM w0.254: U2.4 42.06,48.1 43.08,47.08 43.08,46.13 43.31,45.9 43.31,44.44 v2(43.18,44.31) 43.05,44.31 v1(42.42,44.95)
FAN7_LED_G: length 100
  TOP w0.254: R14.1 69.37,47.53 68.83,47.53 68.58,47.28 68.58,38.6 67.06,37.07 56.64,37.07 55.37,35.8 55.37,19.3 51.07,15 34.1,15 16.76,32.33 v2(16.76,33.64) ; CONN1.5 v2(8.99,32.98)
  BOTTOM w0.254: v2(16.76,33.64) v1(9.91,33.64) 9.65,33.64 v2(8.99,32.98)
FAN7_LED_G1: length 3.9
  TOP w0.254: LED1.C1 v2(71.75,46.99) 70.81,46.99 R14.2
  BOTTOM w0.254: v1(71.63,45.96) 71.75,46.09 v2(71.75,46.99)
FAN7_LED_R: length 98.9
  TOP w0.254: CONN1.7 v2(9.12,31.71) ; R13.1 69.5,48.04 68.62,48.04 68.07,47.49 68.07,38.81 66.85,37.58 56.43,37.58 54.86,36.01 54.86,19.51 50.86,15.5 34.31,15.5 17.42,32.39 v2(17.42,32.75)
  BOTTOM w0.254: v2(17.42,32.75) 16.99,32.32 v1(16.13,32.32) 9.73,32.32 v2(9.12,31.71)
FAN7_LED_R1: length 3.9
  TOP w0.254: LED1.C2 v2(71.75,48.39) 70.81,48.39 R13.2
  BOTTOM w0.254: v2(71.75,48.39) v1(71.75,49.52)
FAN7_OUT_PWM: length 9.5
  TOP w0.254: v2(44.07,44.31) 43.88,44.13 43.88,43.69 R5.1
  BOTTOM w0.254: U2.3 44.6,48.02 43.59,47 43.59,46.34 43.81,46.11 43.81,44.57 v2(44.07,44.31) 44.09,44.31 v1(44.73,44.95)
FAN7_PRESENT: length 61.3
  TOP w0.254: CONN1.21 8.83,22.82 v2(8.93,22.72) ; v2(31.24,21.71) 31.24,21.96 31.94,22.66 31.94,35.79 33.25,37.1 36.04,37.1 36.32,36.82 36.32,36.64 R1.2 36.7,36.62 36.7,37.2 31.75,42.15 31.75,50.94 U2.16
  BOTTOM w0.254: v2(8.93,22.72) v1(10.67,22.72) 11.68,21.71 v2(31.24,21.71)
FAN7_PWM_P: length 6.7
  TOP w0.254: 45.72,42.91 v2(45.72,41.39) 46.12,40.99 Q1.D ; 45.72,42.91 R6.1 ; 45.72,42.91 45.27,42.46 R5.2 R4.2
  BOTTOM w0.254: v2(45.72,41.39) 46.35,42.03 v1(46.35,42.28)
FAN7_S_GND: length 4.4
  TOP w0.381: Q1.S 47.69,37.26 v1(47.75,37.2) v2(49.02,37.2)
  BOTTOM w0.381: v2(49.02,37.2) v1(47.75,37.2)
FAN7_SENSOR_IN: length 79.5
  TOP w0.254: CONN1.13 v2(8.99,27.9) ; R9.1 49.15,42.28 48.49,41.62 48.49,39.75 53.85,34.39 53.85,19.93 50.44,16.52 35.1,16.52 25.02,26.6 v2(25.02,28.06)
  BOTTOM w0.254: v2(25.02,28.06) v1(24.26,28.82) 9.91,28.82 v2(8.99,27.9)
FAN7_SENSOR_IN_R: length 9.4
  TOP w0.254: v2(48.64,44.57) 49.15,44.05 R9.2
  BOTTOM w0.254: v2(48.64,44.57) 48.51,44.69 v1(47.14,44.69) U2.2
FAN7_SENSOR_OUT: length 76.8
  TOP w0.254: CONN1.15 v2(8.93,26.63) ; R8.2 49.15,39.8 54.36,34.6 54.36,19.72 50.65,16.01 34.52,16.01 24.13,26.4 v2(24.13,27.04)
  BOTTOM w0.254: v2(24.13,27.04) 23.75,27.42 v1(21.59,27.42) 9.72,27.42 v2(8.93,26.63)
FAN7_SENSOR_OUT_R: length 13
  TOP w0.254: R8.1 49.81,41.75 49.81,44.48 49.56,44.73 v2(49.41,44.73)
  BOTTOM w0.254: U2.1 49.68,45.48 49.41,45.21 v2(49.41,44.73) 49.41,44.21 v1(48.14,42.94)
FAN7F_VCP: length 3.4
  TOP w0.254: U3.4 48.51,22.86 48.9,22.48 v2(48.9,22.21) 48.9,21.13 C17.2
  BOTTOM w0.254: v1(48.77,21.2) 48.9,21.32 v2(48.9,22.21)
FAN7R_VCP: length 3.5
  TOP w0.254: v1(40.19,21.07) v2(40.19,22.21) 39.75,22.66 U1.4
  BOTTOM w0.254: v1(40.19,21.07) v2(40.19,22.21)
FAN8_IN_PWM: length 11.4
  TOP w0.254: R25.1 109.6,42.41 109.6,42.83 v2(109.53,42.9)
  BOTTOM w0.254: v1(108.85,42.29) 109.46,42.9 v2(109.53,42.9) 109.55,42.92 109.55,42.98 109.73,43.16 109.73,43.8 111.9,45.97 111.9,46.97 110.96,47.9 U7.4
FAN8_LED_G: length 173.3
  TOP w0.254: CONN1.10 14.25,30.44 17.93,26.76 17.93,12.3 26.08,4.15 34.69,4.15 42.48,11.95 81.51,11.95 88.35,18.78 109.11,18.78 113.67,23.34 113.67,29.87 116.08,32.28 v2(116.08,32.5) ; R37.1 v2(141.1,43.3)
  BOTTOM w0.254: v2(141.1,43.3) 141.1,42.53 v1(140.84,42.28) 137.52,38.95 132.87,38.95 132.33,39.49 128.52,39.49 126.49,37.45 126.49,35.29 122.76,31.56 117.02,31.56 v2(116.08,32.5)
FAN8_LED_G1: length 4
  TOP w0.254: LED2.C1 141.36,46.99 141.1,46.72 v2(141.1,46.09) R37.2
  BOTTOM w0.254: v2(141.1,46.09) 141.35,46.09 v1(141.86,45.58)
FAN8_LED_R: length 171.9
  TOP w0.254: R36.1 v2(140.08,43.3) ; v2(117.22,32.63) 117.14,32.63 114.17,29.66 114.17,23.13 109.32,18.28 88.56,18.28 81.72,11.44 42.69,11.44 34.9,3.65 25.87,3.65 17.42,12.09 17.42,26.55 14.8,29.17 CONN1.12
  BOTTOM w0.254: v2(117.22,32.63) 117.78,32.07 122.55,32.07 125.98,35.5 125.98,37.66 128.31,39.99 132.54,39.99 133.08,39.46 137.31,39.46 138.68,40.84 v1(138.68,41.39) 140.08,42.79 v2(140.08,43.3)
FAN8_LED_R1: length 6.1
  TOP w0.254: LED2.C2 140.98,48.39 140.08,47.49 v2(140.08,46.22) R36.2
  BOTTOM w0.254: v2(140.08,46.22) 139.45,46.85 v1(139.32,46.85)
FAN8_OUT_PWM: length 11.5
  TOP w0.254: v2(110.36,42.9) 110.18,42.72 110.18,42.36 R27.1
  BOTTOM w0.254: v1(111.1,42.36) 110.55,42.9 v2(110.36,42.9) 110.36,42.92 110.24,43.05 110.24,43.59 112.41,45.76 112.41,46.86 113.5,47.96 U7.3
FAN8_PRESENT: length 121.5
  TOP w0.254: CONN1.24 14.76,21.55 16.64,19.67 16.76,19.67 v2(16.76,19.67) ; v2(74.42,17.77) 77.98,21.32 77.98,35.8 79.4,37.22 93.82,37.22 96.74,40.15 98.65,40.15 99.13,39.66 R22.2 99.52,39.49 101.07,41.03 101.07,46.62 100.8,46.89 U7.16
  BOTTOM w0.254: v2(74.42,17.77) 74.4,17.77 v1(73.76,17.13) 73,16.37 45.95,16.37 45.09,17.23 22.84,17.23 20.4,19.67 16.77,19.67 v2(16.76,19.67)
FAN8_PWM_P: length 10.1
  TOP w0.254: R25.2 R27.2 110.8,41.19 111.25,41.64 R28.1 111.96,40.91 v2(111.17,40.12) 109.86,40.12 108.84,39.1 Q2.D
  BOTTOM w0.254: v1(112.39,40.12) v2(111.17,40.12)
FAN8_S_GND: length 4.3
  TOP w0.381: v2(109.79,36.82) Q2.S 109.09,35 R26.2
  BOTTOM w0.381: v2(109.79,36.82) 109.86,36.88 v1(109.86,37.83)
FAN8_SENSOR_IN: length 143.8
  TOP w0.254: v2(18.59,25.13) 19.25,24.47 19.25,21.91 18.95,21.6 18.95,12.73 26.5,5.17 34.26,5.17 42.06,12.96 81.09,12.96 87.93,19.8 108.69,19.8 112.65,23.76 112.65,30.55 113.79,31.69 113.79,34.91 115.7,36.82 115.7,40.88 R29.1 ; CONN1.18 v2(13.05,25.36)
  BOTTOM w0.254: v2(13.05,25.36) 13.21,25.52 v1(16.38,25.52) 18.21,25.52 v2(18.59,25.13)
FAN8_SENSOR_IN_R: length 9.2
  TOP w0.254: R29.2 115.39,43.11 v2(115.44,43.17)
  BOTTOM w0.254: U7.2 116.04,46.94 115.44,46.34 v1(115.44,44.18) v2(115.44,43.17)
FAN8_SENSOR_OUT: length 143.8
  TOP w0.254: v2(18.59,23.79) 18.44,23.64 18.44,12.52 26.29,4.66 34.48,4.66 42.27,12.46 81.3,12.46 88.14,19.29 108.9,19.29 113.16,23.55 113.16,30.34 114.3,31.48 114.3,34.68 116.2,36.58 116.2,40.81 R30.2 ; CONN1.20 v2(13.05,24.09)
  BOTTOM w0.254: v2(18.59,23.79) 18.54,23.74 v1(14.1,23.74) 13.31,23.74 13.05,23.99 v2(13.05,24.09)
FAN8_SENSOR_OUT_R: length 9.8
  TOP w0.254: v2(116.71,43.14) 116.59,43.02 R30.1
  BOTTOM w0.254: v2(116.71,43.14) v1(116.71,45.71) 116.71,46.22 118.58,48.08 U7.1
FAN8F_VCP: length 3.5
  TOP w0.254: C46.2 v2(105.53,26.15) 105.09,26.59 U6.4
  BOTTOM w0.254: v1(105.54,25.01) 105.54,26.15 v2(105.53,26.15)
FAN8R_VCP: length 3.3
  TOP w0.254: U5.4 81.39,27.92 v2(81.02,27.54) C35.2
  BOTTOM w0.254: v2(81.02,27.54) v1(79.88,27.54)
FAN_12V: length 61
  TOP w0.254: 135.71,35.73 136.3,36.32 U8.9
  TOP w0.381: C53.1 v2(126.24,20.05) ; 82.42,34.28 82.53,34.38 C36.2 83.14,35.22 83.06,35.29 ; v2(125.09,19.67) C52.1 124.39,18.73 124.33,18.78 ; C20.1 60.23,31.39 C21.1 61.19,30.32 v2(60.83,29.96) ; v2(110.74,34.91) 110.74,38.13 113.99,41.37 R28.2 ; v2(34.67,22.34) 34.72,22.39 C6.2 35.57,20.94 L2.1 ; v2(99.82,26.4) 100.13,26.71 C44.2 100.91,25.26 L8.1 ; R6.2 47.83,42.84 v2(47.83,40.08) ; R16.2 v2(75.06,30.57) ; C22.1 61.98,31.16 61.98,30.09 v2(61.85,29.96) ; 44.32,22.34 44.38,22.39 C16.2 44.96,20.56 L4.1 ; 128.02,18.78 127.96,18.73 C54.1 v2(127.25,19.67)
  TOP w0.508: 122.17,28.69 122.17,30.09 124.71,32.63 129.79,32.63 130.43,33.26 131.06,33.26 132.46,34.66 D2.C 134.64,34.66 135.71,35.73
  BOTTOM w0.381: v2(40.64,35.93) v1(39.5,35.93) ; v2(47.83,40.08) 47.83,39.92 v1(50.42,37.33) v2(50.42,35.68) ; v2(33.83,33.71) v1(33.83,32.68) ; v2(34.91,35.32) 34.95,35.32 v1(35.69,36.06) ; v1(41.66,34.79) 41.66,35.08 v2(42.28,35.7)
  vias: v2(33.78,34.52) v2(33.86,22.34) v2(33.86,21.45) v2(34.04,35.29) v2(33.99,20.64) v2(34.74,33.7) v2(34.77,34.52) v2(34.8,21.45) v2(34.8,20.56) v2(40.64,35.04) v2(40.77,34.15) v2(41.45,35.93) v2(42.7,19.37) v2(43.18,20.04) v2(43.22,18.74) v2(43.67,20.69) v2(43.97,19.05) v2(44.79,19.1) v2(62.74,29.96) v2(80.52,35.93) v2(80.52,35.07) v2(81.41,35.93) v2(81.41,35.07) v2(82.32,35.09) v2(82.42,35.93) v2(90.55,25.01) v2(91.69,25.01) v2(92.46,26.66) v2(92.46,25.77) v2(93.34,26.66) v2(93.34,25.77) v2(98.93,26.53) v2(98.93,25.64) v2(98.93,24.75) v2(99.82,25.59) v2(99.82,24.75) v2(105.6,35.14) v2(105.92,32.47) v2(106.41,35.07) v2(107.05,32.63) v2(107.31,34.28) v2(107.31,33.47) v2(115.82,24.88) v2(116.08,28.94) v2(116.08,26.91) v2(116.71,22.21) v2(117.09,19.8) v2(117.35,27.04) v2(117.35,24.88) v2(117.47,29.07) v2(117.98,22.21) v2(118.75,19.8) v2(119.13,27.17) v2(119.25,29.07) v2(119.63,24.75) v2(119.76,22.34) v2(120.52,19.8) v2(120.9,28.94) v2(121.16,27.04) v2(121.54,24.88) v2(121.79,22.21) v2(121.79,19.93) v2(123.32,24.5) v2(123.32,22.98) v2(123.32,21.71) v2(123.32,20.44) v2(123.32,19.17) v2(124.97,22.98) v2(124.97,20.94) v2(125.09,21.96) v2(125.98,22.47) v2(126.11,23.61) v2(126.11,21.32) v2(127.25,22.47) v2(127.25,21.32) v2(127.38,23.48) v2(128.14,22.72)
FAN_12V_PDU: length 18.6
  TOP w0.381: 144.27,24.25 C60.1 145.21,23.18 145.29,23.1 ; C59.1 144.4,25.26 ; 144.4,26.28 C58.1 145.21,26.99 144.91,27.29
  TOP w0.508: R40.2 146.56,38.92 146.56,29.96 145.41,28.82 v2(143.76,28.82)
  vias: v1(138.3,28.69) v1(138.71,26.4) v1(138.94,18.66) v1(142.11,18.78) v1(142.75,27.55) v2(131.57,14.97) v2(131.95,16.75) v2(133.1,14.85) v2(134.11,16.75) v2(134.62,13.45) v2(135,14.85) v2(135.76,13.45) v2(136.14,16.75) v2(136.27,14.09) v2(136.91,14.85) v2(138.18,21.45) v2(138.3,19.67) v2(138.3,17.9) v2(138.3,16.63) v2(138.81,14.72) v2(139.7,21.45) v2(139.7,19.67) v2(139.83,17.9) v2(140.08,16.63) v2(140.84,14.72) v2(141.1,21.45) v2(141.48,25.13) v2(141.48,23.1) v2(141.48,19.67) v2(141.48,17.9) v2(141.6,28.82) v2(141.6,26.53) v2(141.99,16.5) v2(142.37,14.72) v2(142.62,28.82) v2(142.62,26.53) v2(142.62,21.45) v2(142.75,25.01) v2(142.75,23.1) v2(143,19.67) v2(143.13,17.77) v2(143.64,26.53) v2(143.64,25.01) v2(143.64,16.63) v2(143.89,23.1) v2(144.53,21.45) v2(144.65,19.67) v2(144.78,17.77)
FAN_TOP_HS_PGD: length 163.9
  TOP w0.254: CONN1.29 5.66,17.74 4.65,16.73 4.65,13.58 4.9,13.32 v2(8.13,13.32) 15.48,13.32 25.66,3.14 35.11,3.14 42.9,10.93 81.93,10.93 88.77,17.77 109.58,17.77 114.68,22.87 114.68,29.45 116.46,31.23 121.92,31.23 127,36.31 128.14,36.31 128.71,36.88 129.42,36.88 R31.1 C56.1 132.33,37.48 133.93,35.88 134.96,35.88 135.9,36.82 U8.8
  BOTTOM w0.254: v1(9.4,13.32) v2(8.13,13.32)
FB_VDD3P3: length 6.8
  TOP w0.381: U4.5 73.18,27.39 R17.1 73.31,26.25 C31.2 R18.1 v2(75.14,26.2)
  BOTTOM w0.254: v2(75.14,26.2) 75.18,26.15 v1(76.33,26.15)
HS_GATE: length 22.1
  TOP w0.254: U8.10 v2(136.79,35.18)
  TOP w0.508: 128.65,24.85 128.65,23.99 v2(129.16,23.48)
  BOTTOM w0.508: v2(136.79,35.18) v1(135.51,33.9) 135.51,22.98 134.75,22.21 130.43,22.21 v2(129.16,23.48)
HS_MOS_D:
  vias: v1(126.62,29.45) v2(123.86,30.21) v2(123.86,29.33) v2(123.86,28.44) v2(123.86,27.55) v2(123.86,26.51) v2(126.54,31.63) v2(127.4,31.63) v2(128.22,31.66) v2(129.03,31.63) v2(129.87,30.34) v2(129.87,29.45) v2(129.87,28.56) v2(129.87,27.67) v2(129.87,26.79)
HS_OV: length 5.6
  TOP w0.254: U8.4 142.23,37.32 142.49,37.58 v2(142.49,39.18) 142.49,39.81 R39.1 R38.2
  BOTTOM w0.254: v2(142.49,39.18) 142.88,39.56 v1(142.88,40.12)
HS_PWR: length 6.5
  TOP w0.254: R33.2 133.48,37.06 133.97,36.56 v2(134.49,36.56) 134.93,36.56 135.68,37.32 U8.7
  BOTTOM w0.254: v1(133.1,36.06) 133.6,36.56 v2(134.49,36.56)
HS_SENSE: length 15.9
  TOP w0.254: U8.1 142.52,35.82 143.13,35.21 143.13,34.79 142.77,34.43 141.76,34.43 v2(141.59,34.27) 141.22,33.9 136.31,33.9 135.51,33.09 135.51,31.99 135.18,31.66 R34.1
  BOTTOM w0.254: v2(141.59,34.27) 140.98,34.27 v1(140.59,34.66)
HS_TIMER: length 4.4
  TOP w0.254: U8.6 135.46,37.82 134.89,37.25 v2(134.49,37.25) 134.62,37.38 C57.1
  BOTTOM w0.254: v2(134.49,37.25) 134.52,37.22 135.25,37.22 135.28,37.2 v1(135.41,37.2)
HS_UV: length 7.5
  TOP w0.254: v2(144.58,40.83) R40.1 R39.2 143.58,37.65 142.75,36.82 U8.3
  BOTTOM w0.254: v1(145.54,40.76) 144.65,40.76 v2(144.58,40.83)
HS_VIN: length 17.7
  TOP w0.254: U8.2 142.74,36.32 143.44,35.62 D3.C 144.4,35.29 143.03,33.92 142.27,33.92 v2(142.11,33.77) 141.73,33.39 136.53,33.39 136.02,32.88 136.02,31.87 136.22,31.66 R34.2
  BOTTOM w0.254: v1(143,33.26) 142.49,33.77 v2(142.11,33.77)
ILIM_FAN7F: length 3
  TOP w0.254: v1(50.88,23.41) 50.72,23.25 v2(49.91,23.25) U3.5
  BOTTOM w0.254: v2(49.91,23.25) 50.72,23.25 v1(50.88,23.41)
ILIM_FAN7R: length 3.7
  TOP w0.254: U1.5 v2(41,23.25) 41.48,22.77 v1(42.29,22.77)
  BOTTOM w0.254: v2(41,23.25) 41.48,22.77 v1(42.29,22.77)
ILIM_FAN8F: length 3.1
  TOP w0.254: R24.2 v2(106.81,27.29) 106.53,27.57 U6.5
  BOTTOM w0.254: v1(107.06,26.4) 107.06,27.04 v2(106.81,27.29)
ILIM_FAN8R: length 2.9
  TOP w0.254: U5.5 v2(82.22,26.28) 82.22,25.54 R20.2
  BOTTOM w0.254: v1(81.41,25.77) 81.71,25.77 v2(82.22,26.28)
LGND_FAN12V: length 37.4
  TOP w0.254: U8.5 141.59,38.47
  TOP w0.508: R35.1 137.54,40.37 136.22,39.05 C57.2 R33.1 ; R35.1 138.43,41.64 146.05,41.64 147.45,40.25 147.45,29.07 146.12,27.75 C58.2 ; R35.1 138.3,39.99 R38.1 140.77,39.29 v2(141.22,38.84) 141.59,38.47
  BOTTOM w0.381: v2(141.22,38.84) 140.86,38.49 v1(140.37,38.49)
LGND_VDD3P3: length 11.1
  TOP w0.508: R17.2 75.44,27.52 75.95,28.03 v2(75.95,28.56) 75.95,31.36 75.34,31.97 R15.2 72.82,31.97 C29.2
  BOTTOM w0.381: v2(75.95,28.56) 76.07,28.69 v1(76.07,29.71)
PWM_OUT7: length 45.7
  TOP w0.254: Q1.G v2(45.79,40.12) ; CONN1.1 7.13,36.83 v2(7.37,37.07)
  BOTTOM w0.254: v2(45.79,40.12) v1(44.7,40.12) 36.7,40.12 29.72,33.14 23.11,33.14 19.18,37.07 v2(7.37,37.07)
PWM_OUT8: length 128.5
  TOP w0.254: CONN1.4 13.41,34.25 v2(17.42,30.24) 33.68,13.98 80.67,13.98 87.51,20.82 108.27,20.82 111.63,24.18 111.63,31.99 110.74,32.88 108.58,32.88 108.3,33.17 108.3,35.28 Q2.G
  BOTTOM w0.254: v1(16.38,30.09) 17.27,30.09 v2(17.42,30.24)
SS_VDD3P3: length 2.7
  TOP w0.381: C29.1 71.01,32.84 v2(71.01,31.99) U4.8
  BOTTOM w0.254: v2(71.01,31.99) v1(69.98,31.99)
SST_FAN7F: length 3.3
  TOP w0.254: C18.2 50.37,26.99 v2(49.63,26.25) U3.6
  BOTTOM w0.254: v2(49.63,26.25) 50.04,26.66 v1(50.55,26.66)
SST_FAN7R: length 3.1
  TOP w0.254: C12.2 42.26,26.25 v2(41.27,26.25) U1.6
  BOTTOM w0.254: v2(41.27,26.25) 41.4,26.13 v1(41.4,25.26)
SST_FAN8F: length 3.2
  TOP w0.254: U6.6 v2(106.55,30.57) 107.27,30.57 C48.2
  BOTTOM w0.254: v2(106.55,30.57) 106.58,30.6 v1(107.57,30.6)
SST_FAN8R: length 3.1
  TOP w0.254: U5.6 v2(85.22,26.28) 85.22,25.49 C37.2
  BOTTOM w0.254: v1(86.23,26.28) v2(85.22,26.28)
SW_VDD3P3: length 7.3
  TOP w0.381: R12.2 58.21,28.38 D1.C
  TOP w0.508: C23.2 v2(64.44,32.63)
  BOTTOM w0.508: v2(63.88,28.56) 63.75,28.69 v1(63.75,29.96) 63.53,30.19 63.53,31.71 v2(64.44,32.63)
SW_VDD3P3_PLL_C: length 3.1
  TOP w0.381: R12.1 C19.1 v2(57.4,26.35)
  BOTTOM w0.254: v2(57.4,26.35) 57.53,26.48 v1(57.53,27.42)
VREG5_VDD3P3: length 3.7
  TOP w0.381: C33.1 73.18,28.66 v2(72.39,28.66) v1(71.01,28.66)
  BOTTOM w0.254: v2(72.39,28.66) v1(71.01,28.66)

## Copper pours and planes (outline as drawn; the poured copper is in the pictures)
GND on TOP (solid shape): 85.93,41.27 99.44,41.27 99.44,40.64 85.3,40.64 85.3,53.34 65.17,53.34 65.17,40.64 49.89,40.64 49.89,41.11 50.05,41.27 64.54,41.27 64.54,53.97 85.93,53.97
GND on TOP (solid shape): 17.49,41.27 26.16,41.27 26.16,40.64 16.86,40.64 16.86,53.34 1.65,53.34 1.65,1.65 148.35,1.65 148.35,53.34 133.61,53.34 133.61,40.64 124.58,40.64 124.58,41.27 132.98,41.27 132.98,53.97 148.98,53.97 148.98,1.02 1.02,1.02 1.02,53.97 17.49,53.97
GND on BOTTOM (solid shape): 32.64,55.8 32.64,47.48 33.84,46.28 33.84,44.3 33.82,44.27 31.22,44.27 31.12,44.37 31.12,55.8 31.22,55.9 32.54,55.9
GND on BOTTOM (solid shape): 40.26,55.83 40.26,47.47 41.58,46.15 41.58,44.4 41.43,44.25 38.86,44.25 38.72,44.39 38.72,55.79 38.84,55.9 40.18,55.9
GND on BOTTOM (solid shape): 101.54,55.78 101.54,47.58 102.82,46.31 102.82,44.38 102.69,44.25 100.12,44.25 100.02,44.35 100.02,55.78 100.12,55.89 101.44,55.89
GND on BOTTOM (solid shape): 109.16,55.81 109.16,47.45 110.48,46.13 110.48,45.63 109.08,44.23 107.76,44.23 107.62,44.37 107.62,55.77 107.74,55.89 109.08,55.89
GND on TOP: 50.61,41.21 64.53,41.21 64.78,41.46 64.78,44.19 64.66,44.3 64.66,53.54 64.99,53.87 85.57,53.87 85.82,53.62 85.82,41.33 85.97,41.18 95.75,41.18 96.09,40.84 96.09,39.74 93.93,37.58 80.48,37.58 80.01,38.05 80.01,48.74 79.14,49.61 69.01,49.61 67.68,48.27 67.68,39.39 66.26,37.97 52.14,37.97 50.33,39.78 50.33,40.93
GND on TOP: 100.23,35.59 100.23,31.82 101.96,30.09 102.07,30.09 102.27,29.9 106.85,29.9 107.14,29.61 108.88,29.61 108.89,29.6 109.16,29.6 109.55,29.21 109.55,25.28 109.18,24.91 107.27,24.91 107.06,25.13 107.06,25.98 107.06,25.98 107.06,26.53 107.23,26.7 108.83,26.7 108.95,26.83 108.95,27.72 108.86,27.81 107.99,27.81 107.56,28.24 100.38,28.24 100.18,28.44 100.18,29.4 98.45,31.13 98.45,31.15 98.09,31.51 98.09,35.23 98.61,35.75 100.07,35.75
GND on TOP: 57.66,25.41 58.83,25.41 59,25.23 59,23.89 58.75,23.64 56.09,23.64 55.95,23.78 55.95,24.8 56.02,24.87 57.11,24.87
GND on TOP: 69.73,34.19 69.73,27.08 70.25,26.56 72,26.56 72.27,26.29 72.27,24.39 72.08,24.2 71.4,24.2 71.06,24.55 67.41,24.55 67.06,24.2 64.53,24.2 64.4,24.33 64.4,27.37 64.73,27.7 66.71,27.7 67.22,28.22 67.22,32.61 66.49,33.34 62.92,33.34 62.75,33.17 62.75,32.87 62.62,32.74 58.91,32.74 58.59,33.06 58.59,34.83 58.9,35.14 68.78,35.14
GND on TOP: 84.62,34.85 91.06,34.85 91.73,34.18 91.73,31.77 91.52,31.56 87.88,31.56 87.48,31.16 85.2,31.16 84.56,30.53 84.56,24.29 84.56,24.29 84.56,23.36 84.12,22.92 80.14,22.92 79.58,23.47 79.58,25.93 79.67,26.01 80.77,26.01 81,25.79 81,24.35 81.2,24.15 82.56,24.15 82.9,24.49 82.9,33.19 83.43,33.72 84.34,33.72 84.5,33.87 84.47,33.9 84.47,34.77 84.55,34.77
GND on TOP: 138.56,13.58 141.48,13.58 141.86,13.2 141.86,8.24 141.22,7.61 128.91,7.61 127.89,8.62 127.89,14.47 124.84,17.51 124.84,17.9 128.27,17.9 129.29,16.88 129.29,11.67 129.79,11.16 136.14,11.16
GND on TOP: 119.12,1.14 119.01,1.25 1.42,1.25 1.11,1.56 1.11,53.58 1.41,53.89 16.94,53.89 17.4,53.43 17.4,41.21 17.57,41.04 23.27,41.04 23.72,40.59 23.72,29.54 20.75,29.54 13.89,36.39 5.87,36.39 5.42,35.94 5.42,13.95 7,12.36 15.14,12.36 22.41,5.09 22.41,5.08 24.68,2.8 35.44,2.8 42.87,10.24 84.27,10.24 90.88,16.85 111.18,16.85 112.64,15.38 112.64,11.87 118.92,5.6 120.58,5.6 121.38,4.79 123.94,4.79 126.15,7 141.7,7 142.77,8.07 142.77,12.53 142.7,12.61 142.7,13.64 146.01,16.96 146.01,26.75 146.92,27.65 148.48,27.65 148.87,27.27 148.87,1.62 148.39,1.14 ; 1 cut-out
GND on TOP: 34.37,32.9 36.41,32.9 36.59,32.73 36.59,26.08 37.13,25.53 42.47,25.53 42.63,25.37 42.63,23.52 42.46,23.35 41.76,23.35 41.25,23.86 34.77,23.86 34.09,24.53 34.09,32.63
GND on TOP: 41.41,33.01 42.7,33.01 42.97,32.74 42.97,29.46 43.79,28.64 43.79,27.79 45.96,25.62 49.77,25.62 50.49,26.33 51.17,26.33 51.38,26.12 51.38,24.39 50.89,23.9 45.7,23.9 45.46,23.66 44.27,23.66 43.78,24.16 43.78,26.48 41.33,28.92 41.33,28.98 40.82,29.49 40.82,32.43
GND on TOP: 133.19,53.94 148.59,53.94 148.93,53.6 148.93,49.61 148.64,49.32 140.79,49.32 139.36,47.9 139.36,42.81 138.76,42.21 137.48,42.21 137.05,41.78 133.34,41.78 133.02,42.1 133.02,53.77
GND on BOTTOM: 1.02,1.02 1.02,53.97 17.49,53.97 17.49,41.27 31.05,41.27 31.05,43.18 50.52,43.18 50.52,41.27 64.54,41.27 64.54,53.97 85.93,53.97 85.93,41.27 99.95,41.27 99.95,43.28 119.42,43.28 119.42,41.27 132.98,41.27 132.98,53.97 148.98,53.97 148.98,1.02
GND on G2: 1.02,1.02 1.02,53.97 17.49,53.97 17.49,41.27 31.05,41.27 31.05,55.28 50.52,55.28 50.52,41.27 64.54,41.27 64.54,53.97 85.93,53.97 85.93,41.27 99.95,41.27 99.95,55.28 119.42,55.28 119.42,41.27 132.98,41.27 132.98,53.97 148.98,53.97 148.98,1.02
GND on V3: 1.02,1.02 1.02,53.97 17.49,53.97 17.49,41.27 31.05,41.27 31.05,55.88 31.25,56.08 50.32,56.08 50.52,55.88 50.52,41.27 64.54,41.27 64.54,53.97 85.93,53.97 85.93,41.27 99.95,41.27 99.95,55.88 100.15,56.08 119.22,56.08 119.42,55.88 119.42,41.27 132.98,41.27 132.98,53.97 148.98,53.97 148.98,1.02
GND_1 on TOP (solid shape): outline of 235 points within 24.5,33.6 31.5,40.6
GND_1 on BOTTOM (solid shape): outline of 235 points within 24.5,33.6 31.5,40.6
GND_2 on TOP (solid shape): outline of 235 points within 118.5,33.6 125.5,40.6
GND_2 on BOTTOM (solid shape): outline of 235 points within 118.5,33.6 125.5,40.6
GND_3 on TOP (solid shape): outline of 235 points within 118.5,8.6 125.5,15.6
GND_3 on BOTTOM (solid shape): outline of 235 points within 118.5,8.6 125.5,15.6
GND_4 on TOP (solid shape): outline of 235 points within 24.5,8.6 31.5,15.6
GND_4 on BOTTOM (solid shape): outline of 235 points within 24.5,8.6 31.5,15.6
VCC_12P_FAN7_IN on BOTTOM (solid shape): 35.18,55.3 35.18,47.5 35.84,46.84 35.84,44.4 35.76,44.32 35.74,44.32 35.58,44.31 35.44,44.27 34.3,44.27 34.2,44.37 34.2,46.65 33.68,47.17 33.68,55.27 33.78,55.37 35.1,55.37
